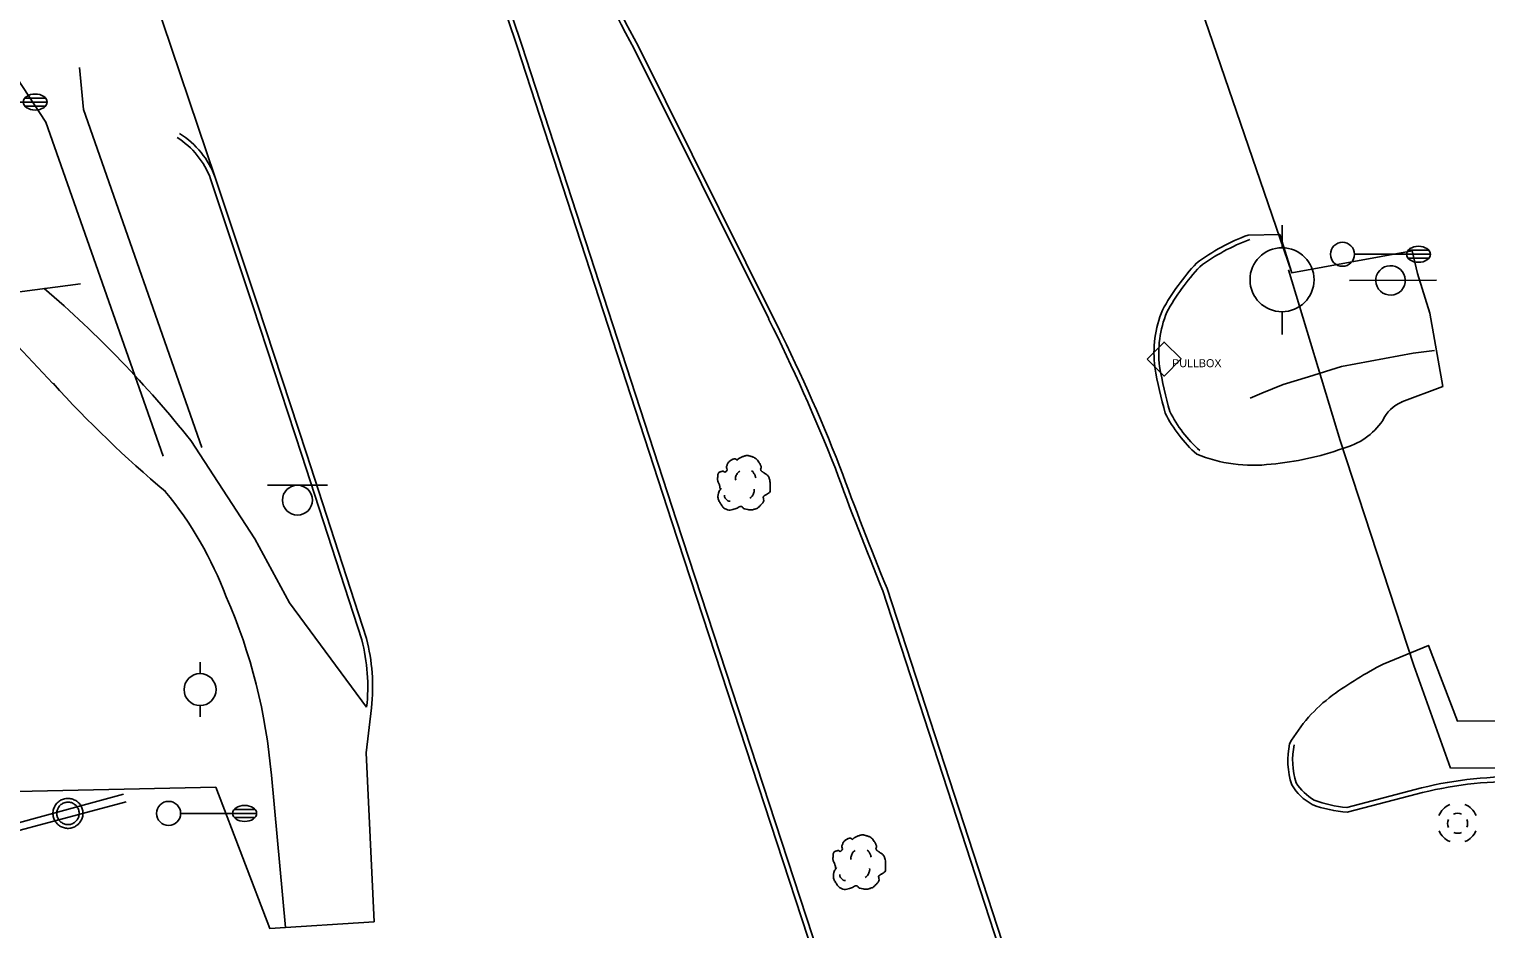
# Model space of a CAD drawing. Extents: x 2145380 to 2156929, y 139568 to 149130.
# Drawn here: x 2147379.3 to 2147561.3, y 142646.5 to 142759 of the extents above; entities that cross this region are included whole.
import ezdxf

# ---------------------------------------------------------------- set-up
doc = ezdxf.new("R2010")
doc.units = 0
for name, color, linetype in [('Default', 7, 'Continuous'), ('TOPO_Asphalt', 7, 'Continuous'), ('TOPO_Concrete', 7, 'Continuous'), ('TOPO_Curb Back', 7, 'Continuous'), ('TOPO_Dirt Grav', 7, 'Continuous'), ('TOPO_DRAIN_Manhole', 7, 'Continuous'), ('TOPO_Fence', 7, 'Continuous'), ('TOPO_Flowline', 7, 'Continuous'), ('TOPO_Guardrail', 7, 'Continuous'), ('TOPO_Light Pole', 7, 'Continuous'), ('TOPO_Power Pole', 7, 'Continuous'), ('TOPO_Power Pullbox', 7, 'Continuous'), ('TOPO_Sign', 7, 'Continuous'), ('TOPO_Tree', 7, 'Continuous')]:
    doc.layers.add(name, color=color, linetype=linetype)

# ---------------------------------------------------------------- blocks, each defined once
blk = doc.blocks.new('POWPOL')
at = {"layer": 'TOPO_Power Pole'}
for p, q in [((0, 10.16), (0, 17.34)), ((0, -10.16), (0, -17.34))]:
    blk.add_line(p, q, dxfattribs=at)
blk.add_circle((0, 0), 10.16, dxfattribs=at)
blk = doc.blocks.new('LP')
at = {"layer": 'TOPO_Light Pole'}
blk.add_line((3.81, 0), (20.32, 0), dxfattribs=at)
for points in [[(20.32, 0), (27.94, 0)], [(20.32, 0), (23.5, 0)], [(20.83, 1.27), (27.43, 1.27)], [(20.83, 1.27), (23.5, 1.27)], [(23.71, 1.27), (27.43, 1.27)], [(23.71, 0), (27.94, 0)], [(20.83, -1.27), (27.43, -1.27)], [(20.83, -1.27), (23.5, -1.27)], [(23.71, -1.27), (27.43, -1.27)]]:
    blk.add_lwpolyline(points, dxfattribs=at)
blk.add_circle((0, 0), 3.81, dxfattribs=at)
blk.add_ellipse((24.13, 0), major_axis=(3.81, 0), ratio=0.666667, dxfattribs=at)
blk = doc.blocks.new('MHEXST')
at = {"layer": 'TOPO_DRAIN_Manhole'}
for centre, radius, start, end in [((-0.14, 0.26), 12.7, 112.97475, 158.26364), ((-0.14, 0.26), 12.7, 22.07441, 68.69913), ((-0.08, 0.11), 6.35, 157.97219, 204.16105), ((-0.08, 0.11), 6.35, 66.19406, 113.69103), ((-0.08, 0.11), 6.35, 336.80229, 21.40458), ((-0.14, 0.26), 12.7, 202.6921, 248.19382), ((-0.08, 0.11), 6.35, 248.57914, 293.19947), ((-0.14, 0.26), 12.7, 291.79631, 337.30323)]:
    blk.add_arc(centre, radius, start, end, dxfattribs=at)
blk = doc.blocks.new('TREE')
at = {"layer": 'TOPO_Tree'}
for points in [[(-14.07, -0.4), (-14.17, 0.5), (-14.37, 1.38), (-14.6, 2.25), (-14.84, 3.17), (-15.47, 3.96), (-15.66, 4.9), (-15.8, 5.59), (-15.71, 6.31), (-15.66, 7.01), (-15.6, 7.91), (-15.72, 8.8), (-15.13, 9.66), (-14.62, 10.42), (-13.76, 10.49), (-13.02, 10.72), (-12.18, 10.98), (-11.06, 10), (-10.37, 10.72), (-9.4, 11.74), (-10.29, 13.28), (-9.84, 14.42), (-9.56, 15.15), (-9.32, 15.89), (-8.78, 16.54), (-8.18, 17.26), (-7.5, 17.68), (-6.67, 18.13), (-6.14, 18.41), (-5.61, 18.61), (-5.08, 18.66), (-4.55, 18.71), (-4.02, 18.54), (-3.49, 18.13)], [(-3.49, 17.6), (-3.07, 18.27), (-2.58, 18.8), (-1.9, 19.19), (-1.05, 19.68), (-0.19, 19.96), (0.74, 20.24), (1.62, 20.51), (2.51, 20.82), (3.39, 20.77), (4.1, 20.73), (4.8, 20.47), (5.51, 20.24), (6.43, 19.95), (7.32, 19.73), (8.15, 19.19), (9.36, 18.4), (10.02, 17.21), (10.8, 16.01), (11.24, 15.33), (11.58, 14.62), (11.86, 13.89), (12.17, 13.08), (11.37, 12.02), (11.86, 11.25), (12, 11.03), (12.18, 10.86), (12.39, 10.72), (12.91, 10.35), (13.45, 10.02), (13.97, 9.66), (14.7, 9.16), (15.41, 8.68), (16.09, 8.07), (16.7, 7.53), (16.93, 6.73), (17.15, 5.95), (17.59, 4.38), (17.71, 2.77), (17.68, 1.19), (17.65, -0.25), (17.83, -2.22), (16.62, -3.04), (15.47, -3.83), (14.31, -4.58), (13.16, -5.35)], [(-4.21, 5.09), (-4.46, 6.09), (-4.3, 7.21), (-3.84, 8.21), (-3.33, 9.34), (-2.71, 10.27), (-1.64, 10.97)], [(5.89, 11.15), (6.5, 10.68), (6.96, 10.17), (7.36, 9.5), (7.93, 8.56), (8.31, 7.6), (8.46, 6.56)], [(13.16, -5.34), (13.25, -5.81), (13.36, -6.28), (13.45, -6.75), (13.76, -8.52), (12.24, -10.03), (10.8, -11.51), (9.98, -12.34), (9.13, -12.77), (8.15, -13.1), (5.97, -13.83), (3.32, -13.56), (1.27, -13.1), (0.49, -12.92), (-0.06, -11.44), (-0.84, -11.51), (-2.04, -11.61), (-3.28, -12.78), (-4.55, -13.1), (-6.06, -13.47), (-7.77, -14.03), (-9.31, -13.62), (-11.36, -13.09), (-12.84, -11.41), (-14.07, -9.39), (-15.32, -7.35), (-15.61, -5.13), (-15.13, -3.04), (-14.87, -1.89), (-13.91, -0.75), (-13.54, 0.13)], [(-11.38, -4.46), (-11.47, -5.41), (-11.03, -6.32), (-10.09, -7.22), (-9.3, -7.97), (-8.49, -8.26), (-7.7, -8.14)], [(4.79, -6.29), (5.71, -5.66), (6.3, -4.92), (6.81, -3.91), (7.36, -2.81), (7.63, -1.7), (7.54, -0.6)]]:
    blk.add_open_spline(points, degree=3, dxfattribs=at)
blk = doc.blocks.new('pulbox')
at = {"layer": 'Default'}
blk.add_lwpolyline([(-5.38, -0.01), (-0.02, 5.42), (5.4, 0.06), (0.05, -5.36), (-5.38, -0.01)], dxfattribs=at)
blk.add_text('PULLBOX', height=2.54, dxfattribs=at).set_placement((2.54, -2.54))

msp = doc.modelspace()

# ---------------------------------------------------------------- linework, layer by layer
at = {"layer": 'TOPO_Asphalt'}
msp.add_line((2147379.12, 142809.78), (2147402.56, 142740.4), dxfattribs=at)
for points in [[(2147550.86, 142712.35), (2147555.96, 142714.29), (2147554.33, 142723.44), (2147552.81, 142728.43), (2147552.15, 142731.25), (2147537.08, 142728.5), (2147535.58, 142733.28), (2147531.64, 142733.22)], [(2147385.72, 142727.12), (2147356.53, 142723.28), (2147321.06, 142719.66), (2147303.05, 142716.63)], [(2147422.07, 142674.13), (2147421.42, 142668.5), (2147422.4, 142647.38), (2147409.37, 142646.54), (2147402.62, 142664.18), (2147370.09, 142663.49), (2147370.88, 142674.99), (2147369.88, 142689.4), (2147296.13, 142688.43), (2147231.46, 142686.35), (2147183.48, 142688.76)], [(2147548.5, 142679.57), (2147554.17, 142681.92), (2147557.82, 142672.43), (2147585.42, 142672.53), (2147630.17, 142671.16), (2147682.2, 142673.05)]]:
    msp.add_lwpolyline(points, dxfattribs=at)
for centre, radius, start, end in [((2147552.55, 142708.21), 4.47, 112.1319, 156.143), ((2147541.31, 142714.98), 8.7, 284.2966, 325.2617), ((2147532.24, 142722.89), 18.45, 247.616, 277.0787), ((2147531.61, 142739.21), 34.75, 274.7926, 289.9424), ((2147571.02, 142635.94), 49.1, 117.298, 125.9626), ((2147553.77, 142659.98), 19.51, 126.4214, 150.3788)]:
    msp.add_arc(centre, radius, start, end, dxfattribs=at)
at = {"layer": 'TOPO_Concrete'}
for points in [[(2147396.06, 142705.59), (2147381.39, 142747.31), (2147377.04, 142753.94)], [(2147385.61, 142754.15), (2147386.11, 142748.91), (2147400.87, 142706.65)]]:
    msp.add_lwpolyline(points, dxfattribs=at)
at = {"layer": 'TOPO_Curb Back'}
for points in [[(2147459.61, 142697.37), (2147440.29, 142756.78), (2147423.84, 142805.62), (2147404.95, 142862.58), (2147403, 142867.87), (2147393.71, 142894.97)], [(2147460.18, 142697.55), (2147440.86, 142756.97), (2147424.41, 142805.81), (2147405.51, 142862.78), (2147403.56, 142868.07), (2147394.27, 142895.2)], [(2147454.92, 142756.5), (2147471.72, 142722.73)], [(2147455.45, 142756.78), (2147472.25, 142723)], [(2147407.26, 142724.37), (2147401.98, 142740.25)], [(2147407.84, 142724.54), (2147402.56, 142740.4)], [(2147420.87, 142682.6), (2147413.39, 142705.72), (2147407.26, 142724.37)], [(2147421.44, 142682.77), (2147413.96, 142705.9), (2147407.84, 142724.54)], [(2147497.63, 142580.22), (2147479.71, 142636.01), (2147459.61, 142697.37)], [(2147498.21, 142580.4), (2147480.28, 142636.2), (2147460.18, 142697.55)], [(2147485.93, 142688.87), (2147505.7, 142628.2), (2147529.94, 142555.48), (2147551.02, 142491.19), (2147560.55, 142462.86)], [(2147486.51, 142689.04), (2147506.27, 142628.39), (2147530.51, 142555.67), (2147551.59, 142491.38), (2147561.18, 142462.86)], [(2147543.97, 142661.66), (2147551.7, 142663.68)], [(2147544.02, 142661.06), (2147551.86, 142663.1)]]:
    msp.add_lwpolyline(points, dxfattribs=at)
for centre, radius, start, end in [((2147535.4, 142801.47), 92.2, 197.8061, 209.1932), ((2147535.4, 142801.47), 91.6, 197.8023, 209.2021), ((2147392.21, 142736.62), 11.02, 20.1005, 57.6944), ((2147392.21, 142736.62), 10.42, 20.3848, 57.6944), ((2147540.39, 142709.46), 25.32, 110.2019, 126.9019), ((2147540.39, 142709.46), 24.72, 110.2019, 126.773), ((2147548.97, 142707.92), 32.26, 137.5085, 150.4182), ((2147548.97, 142707.92), 31.66, 137.6095, 150.3459), ((2147534.31, 142718.43), 14.44, 157.9892, 186.9382), ((2147263.53, 142618.49), 232.82, 21.5593, 26.5986), ((2147263.53, 142618.49), 233.42, 21.5573, 26.5984), ((2147534.31, 142718.43), 13.84, 158.1526, 186.8742), ((2147576.79, 142726.62), 57.68, 189.9152, 195.7601), ((2147576.79, 142726.62), 57.08, 189.931, 195.7037), ((2147536.25, 142718.38), 16.11, 206.5858, 228.6529), ((2147536.25, 142718.38), 16.71, 206.3886, 228.6529), ((2147871.1, 142846.48), 416.17, 200.0144, 202.2631), ((2147871.1, 142846.48), 415.57, 200.0133, 202.2631), ((2147399.04, 142676.81), 22.58, 353.3648, 14.8706), ((2147399.04, 142676.81), 23.18, 353.3648, 14.9105), ((2147546.48, 142667.56), 9.88, 167.8776, 198.0821), ((2147546.48, 142667.56), 9.28, 167.8776, 197.6506), ((2147564.78, 142617.38), 48.12, 90.0244, 105.7729), ((2147543.01, 142668.09), 6.93, 211.2729, 240.8411), ((2147543.01, 142668.09), 6.33, 211.897, 240.4314), ((2147564.78, 142617.38), 47.52, 90.0216, 105.78), ((2147545.35, 142677.41), 16.41, 249.582, 265.3466), ((2147545.35, 142677.41), 15.81, 249.7505, 264.9803)]:
    msp.add_arc(centre, radius, start, end, dxfattribs=at)
at = {"layer": 'TOPO_Dirt Grav'}
for points in [[(2147372.21, 142725.34), (2147382.28, 142714.68)], [(2147421.47, 142674.2), (2147411.83, 142687.25), (2147407.52, 142695.26), (2147399.49, 142707.54)], [(2147409.58, 142665.69), (2147411.35, 142646.67)]]:
    msp.add_lwpolyline(points, dxfattribs=at)
for centre, radius, start, end in [((2147291.11, 142621.39), 138.45, 38.4822, 49.4104), ((2147488, 142810.42), 142.62, 222.1637, 229.9976), ((2147360, 142671.36), 46.98, 20.7329, 39.374), ((2147338.99, 142659.71), 70.84, 4.8444, 23.5278)]:
    msp.add_arc(centre, radius, start, end, dxfattribs=at)
at = {"layer": 'TOPO_Fence'}
for p, q in [((2147537.08, 142728.5), (2147523.83, 142767.24)), ((2147552.34, 142679.39), (2147543.14, 142707.52))]:
    msp.add_line(p, q, dxfattribs=at)
msp.add_lwpolyline([(2147613.89, 142644.09), (2147613.51, 142666.68), (2147556.97, 142666.57)], dxfattribs=at)
at = {"layer": 'TOPO_Flowline'}
msp.add_lwpolyline([(2147554.92, 142718.8), (2147552.27, 142718.46), (2147543.32, 142716.79), (2147539.2, 142715.51), (2147536.02, 142714.55), (2147533.34, 142713.45), (2147531.87, 142712.81)], dxfattribs=at)
at = {"layer": 'TOPO_Guardrail'}
for p, q in [((2147543.14, 142707.52), (2147536.66, 142728.88)), ((2147556.94, 142666.59), (2147552.34, 142679.39))]:
    msp.add_line(p, q, dxfattribs=at)
at = {"layer": 'TOPO_Power Pole'}
for points in [[(2147382.28, 142660.92), (2147382.28, 142661.05), (2147382.3, 142661.18), (2147382.32, 142661.31), (2147382.36, 142661.44), (2147382.4, 142661.56), (2147382.45, 142661.69), (2147382.51, 142661.81), (2147382.57, 142661.92), (2147382.65, 142662.03), (2147382.73, 142662.14), (2147382.82, 142662.23), (2147382.92, 142662.33), (2147383.02, 142662.41), (2147383.13, 142662.49), (2147383.24, 142662.56), (2147383.36, 142662.61), (2147383.48, 142662.66), (2147383.6, 142662.71), (2147383.73, 142662.75), (2147383.87, 142662.77), (2147384, 142662.79), (2147384.13, 142662.79), (2147384.26, 142662.79), (2147384.39, 142662.77), (2147384.52, 142662.76), (2147384.64, 142662.72), (2147384.77, 142662.69), (2147384.89, 142662.63), (2147385.02, 142662.58), (2147385.13, 142662.52), (2147385.24, 142662.45), (2147385.35, 142662.36), (2147385.44, 142662.28), (2147385.54, 142662.18), (2147385.62, 142662.08), (2147385.7, 142661.97), (2147385.77, 142661.86), (2147385.84, 142661.74), (2147385.89, 142661.62), (2147385.93, 142661.49), (2147385.97, 142661.37), (2147386, 142661.24), (2147386.01, 142661.11), (2147386.02, 142660.97), (2147386.02, 142660.85), (2147386.01, 142660.71), (2147385.99, 142660.58), (2147385.96, 142660.45), (2147385.92, 142660.33), (2147385.88, 142660.2), (2147385.82, 142660.09), (2147385.77, 142659.97), (2147385.69, 142659.86), (2147385.61, 142659.75), (2147385.52, 142659.65), (2147385.43, 142659.55), (2147385.33, 142659.47), (2147385.22, 142659.39), (2147385.11, 142659.32), (2147385, 142659.25), (2147384.88, 142659.2), (2147384.75, 142659.15), (2147384.62, 142659.11), (2147384.5, 142659.08), (2147384.37, 142659.06), (2147384.23, 142659.05), (2147384.11, 142659.05), (2147383.98, 142659.06), (2147383.85, 142659.07), (2147383.71, 142659.11), (2147383.59, 142659.14), (2147383.47, 142659.19), (2147383.34, 142659.24), (2147383.22, 142659.3), (2147383.11, 142659.37), (2147383, 142659.45), (2147382.9, 142659.53), (2147382.81, 142659.62), (2147382.72, 142659.72), (2147382.64, 142659.83), (2147382.56, 142659.94), (2147382.5, 142660.05), (2147382.44, 142660.17), (2147382.39, 142660.3), (2147382.35, 142660.42), (2147382.32, 142660.55), (2147382.3, 142660.68), (2147382.28, 142660.81), (2147382.28, 142660.92)], [(2147382.75, 142660.92), (2147382.75, 142661.03), (2147382.77, 142661.15), (2147382.79, 142661.26), (2147382.83, 142661.37), (2147382.87, 142661.48), (2147382.92, 142661.58), (2147382.97, 142661.67), (2147383.04, 142661.77), (2147383.11, 142661.86), (2147383.19, 142661.94), (2147383.28, 142662.02), (2147383.38, 142662.09), (2147383.47, 142662.14), (2147383.57, 142662.2), (2147383.68, 142662.24), (2147383.79, 142662.28), (2147383.9, 142662.3), (2147384.01, 142662.32), (2147384.13, 142662.32), (2147384.24, 142662.32), (2147384.35, 142662.31), (2147384.47, 142662.29), (2147384.58, 142662.26), (2147384.68, 142662.22), (2147384.79, 142662.17), (2147384.88, 142662.11), (2147384.98, 142662.05), (2147385.07, 142661.98), (2147385.16, 142661.9), (2147385.23, 142661.81), (2147385.3, 142661.72), (2147385.36, 142661.62), (2147385.42, 142661.52), (2147385.47, 142661.42), (2147385.5, 142661.31), (2147385.53, 142661.2), (2147385.54, 142661.08), (2147385.55, 142660.97), (2147385.55, 142660.86), (2147385.54, 142660.75), (2147385.52, 142660.64), (2147385.5, 142660.52), (2147385.46, 142660.41), (2147385.41, 142660.31), (2147385.36, 142660.21), (2147385.3, 142660.11), (2147385.23, 142660.02), (2147385.15, 142659.94), (2147385.07, 142659.86), (2147384.97, 142659.79), (2147384.88, 142659.73), (2147384.78, 142659.67), (2147384.67, 142659.62), (2147384.57, 142659.58), (2147384.45, 142659.55), (2147384.34, 142659.53), (2147384.22, 142659.52), (2147384.12, 142659.52), (2147384.01, 142659.53), (2147383.9, 142659.54), (2147383.78, 142659.56), (2147383.67, 142659.6), (2147383.57, 142659.65), (2147383.47, 142659.7), (2147383.37, 142659.76), (2147383.27, 142659.83), (2147383.19, 142659.9), (2147383.11, 142659.99), (2147383.03, 142660.08), (2147382.97, 142660.17), (2147382.92, 142660.27), (2147382.87, 142660.37), (2147382.82, 142660.48), (2147382.79, 142660.59), (2147382.77, 142660.7), (2147382.75, 142660.82), (2147382.75, 142660.92)]]:
    msp.add_lwpolyline(points, dxfattribs=at)
at = {"layer": 'TOPO_Sign'}
for points in [[(2147544.29, 142727.52), (2147555.17, 142727.58)], [(2147409.08, 142701.95), (2147416.57, 142701.95)], [(2147412.83, 142701.95), (2147412.83, 142701.95)], [(2147410.96, 142700.08), (2147410.96, 142700.08)], [(2147414.7, 142700.08), (2147414.7, 142700.08)], [(2147412.83, 142698.21), (2147412.83, 142698.21)], [(2147367.41, 142656.86), (2147391.09, 142663.31)], [(2147391.43, 142662.36), (2147367.69, 142656.01)]]:
    msp.add_lwpolyline(points, dxfattribs=at)
for centre, radius, start, end in [((2147549.43, 142727.55), 1.84, 47.4196, 227.4196), ((2147549.43, 142727.55), 1.84, 227.4196, 47.4196), ((2147412.83, 142700.08), 1.87, 90, 180), ((2147412.83, 142700.08), 1.87, 360, 90), ((2147412.83, 142700.08), 1.87, 180, 270), ((2147412.83, 142700.08), 1.87, 270, 0)]:
    msp.add_arc(centre, radius, start, end, dxfattribs=at)

# ---------------------------------------------------------------- block references
at = {"layer": 'TOPO_DRAIN_Manhole', "xscale": 0.19685000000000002, "yscale": 0.19685000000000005}
msp.add_blockref('MHEXST', (2147557.83, 142659.66), dxfattribs=at)
at = {"layer": 'TOPO_Light Pole', "xscale": 0.39370000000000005, "yscale": 0.3937000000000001}
for p in [(2147370.56, 142749.85), (2147543.42, 142730.81), (2147396.73, 142660.92)]:
    msp.add_blockref('LP', p, dxfattribs=at)
at = {"layer": 'TOPO_Power Pole'}
for p, xscale, yscale in [((2147535.87, 142727.63), 0.39370000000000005, 0.3937000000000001), ((2147400.66, 142676.39), 0.19685000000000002, 0.19685000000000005)]:
    msp.add_blockref('POWPOL', p, dxfattribs=dict(at, xscale=xscale, yscale=yscale))
at = {"layer": 'TOPO_Power Pullbox', "xscale": 0.39370000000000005, "yscale": 0.3937000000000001}
msp.add_blockref('pulbox', (2147521.14, 142717.7), dxfattribs=at)
at = {"layer": 'TOPO_Tree', "xscale": 0.19685000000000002, "yscale": 0.19685000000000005}
for p in [(2147468.43, 142701.56), (2147482.85, 142654.14)]:
    msp.add_blockref('TREE', p, dxfattribs=at)

doc.saveas('drawing.dxf')
